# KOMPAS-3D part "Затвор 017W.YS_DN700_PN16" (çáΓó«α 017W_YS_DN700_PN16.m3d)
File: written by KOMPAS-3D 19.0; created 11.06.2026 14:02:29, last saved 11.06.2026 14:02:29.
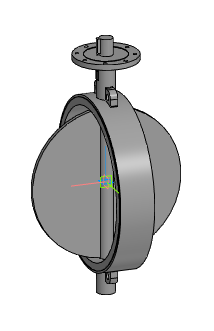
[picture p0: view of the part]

Document properties: Автор: Евгений; Полное имя файла: Z:\3.Личные\kachalov\001_3d для проектировщиков\x.x Тип 017W.Y(S) Затвор дисковый поворотный межфланцевый\_stp_Затвор 017W.YS_DN32-DN1200\Затвор 017W_YS_DN700_PN16.m3d

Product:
- Part/product: Затвор 017W.YS_DN700_PN16

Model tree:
1. Операция без истории:1  (labels: Затвор 017W.YS_DN700_PN16)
